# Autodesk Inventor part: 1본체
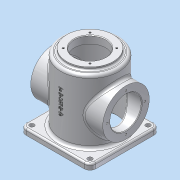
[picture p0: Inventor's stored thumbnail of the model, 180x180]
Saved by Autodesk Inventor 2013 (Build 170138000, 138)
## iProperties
Created: 2015-10
Part Number: 1본체
Material: 알루미늄 6061
Document SubType Name: Modeling
Designer: Administrator
Density: 2.71 g/cm^3
Mass: 986.025 g
Surface Area: 1037.25 cm^2
Volume: 363.847 cm^3
Author: Administrator
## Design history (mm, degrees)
sketch "스케치1"
  geometry: L1 (-60, 60)-(60, 60); L2 (60, 60)-(60, -60); L3 (60, -60)-(-60, -60); L4 (-60, -60)-(-60, 60); 3 further points
  constraints: 8 end point, 2 midpoint, 2 parallel, 2 perpendicular, 1 horizontal, 1 horizontal alignment, 1 vertical alignment
  dimensions: "d0" = 120 distance of L1.start L1.end
extrude "돌출1" new body sketch "스케치1" distance "d2" = 10; taper "d3" = 0 deg
sketch "스케치2"
  geometry: C1 r 50 at (0, 0); 1 further point
  constraints: 1 centre point, 1 coincident
  dimensions: "d4" = 100 diameter of C1
extrude "돌출2" join sketch "스케치2" distance "d6" = 110; taper "d7" = 0 deg
sketch "스케치3"
  geometry: C1 r 40 at (0, 60); 1 further point
  constraints: 1 centre point, 1 vertical alignment
  dimensions: "d8" = 80 diameter of C1; "d10" = 60 distance of C1.centre point (0, 0)
extrude "돌출3" join sketch "스케치3" stored distance "d11" = 124; taper "d12" = 0 deg
sketch "스케치4"
  geometry: C1 r 40 at (0, 0); 1 further point
  constraints: 1 centre point, 1 coincident
  dimensions: "d13" = 80 diameter of C1
extrude "돌출4" join sketch "스케치4" distance "d15" = 5; taper "d16" = 0 deg
sketch "스케치5"
  geometry: L1 (-48.178, 55.165)-(-48.178, 84.835); L2 (-48.178, 84.835)-(48.178, 84.835); L3 (48.178, 84.835)-(48.178, 55.165); L4 (48.178, 55.165)-(-48.178, 55.165); 4 further points
  constraints: 2 midpoint, 2 vertical alignment, 1 horizontal alignment, 2 other
  dimensions: "d17" = 70 distance of point (0, 70) point (0, 0)
feature "엠보싱1" sketch "스케치5" dims "d0" = 120, "d18" = 0.5, "d19" = 0
hole "구멍1" diameter "d22" = 54; stored, may be unused: countersink angle "d26" = 90 deg, drill point angle "d28" = 0 deg; dims "d20" = 10, "d21" = 10, "d23" = 6, "d24" = 54, "d25" = 13, "d27" = 124
sketch "스케치7"
  geometry: L1 (40, 125)-(-40, 125) reference; L2 (-60, 0)-(60, 0) reference; L3 (0, 125)-(0, 0); L4 (0, 125)-(27, 125); L5 (27, 112)-(45, 112); L6 (45, 112)-(45, 0); L7 (27, 125)-(27, 112); L8 (45, 0)-(0, 0)
  constraints: 12 end point, 2 parallel, 2 perpendicular, 2 point on line, 1 collinear, 1 midpoint
  dimensions: "d29" = 54 diameter of L7 L3; "d31" = 90 diameter of L6 L3; "d32" = 13 distance from line of L5.start L1
revolve "회전1" sketch "스케치7" stored, may be unused: angle "d33" = 90 deg
sketch "스케치8"
  geometry: A1 r 32.5 centre (0, 0) between (-22.981, 22.981) and (22.981, 22.981); 3 further points
  constraints: 4 point on circle, 2 horizontal alignment, 2 vertical alignment, 1 centre point, 1 coincident
  dimensions: "d34" = 65 diameter of A1; "d36" = 90 deg dimension on point (0, 0) A1.end A1.start
hole "구멍2" sketch "스케치8" at (-22.981, 22.981), (22.981, 22.981), (-22.981, -22.981), (22.981, -22.981) diameter "d38" = 3.242; stored, may be unused: countersink angle "d42" = 90 deg, drill point angle "d44" = 118 deg; dims "d39" = 8, "d40" = 54, "d41" = 13, "d43" = 10
sketch "스케치10"
  geometry: A1 r 32.5 centre (0, 0) between (32.5, 0) and (0, 32.5); 5 further points
  constraints: 4 point on circle, 3 vertical alignment, 2 horizontal alignment, 1 centre point, 2 other
  dimensions: "d45" = 60 distance of A1.centre point (0, -60); "d46" = 65 diameter of A1
hole "구멍3" sketch "스케치10" at (0, 32.5), (0, -32.5), (-32.5, 0), (32.5, 0) diameter "d47" = 3.242; stored, may be unused: countersink angle "d51" = 90 deg, drill point angle "d53" = 118 deg; dims "d48" = 8, "d49" = 54, "d50" = 13, "d52" = 10
sketch "스케치11"
  geometry: C1 r 4 at (-50, 50); C2 r 4 at (50, 50); C3 r 4 at (50, -50); C4 r 4 at (-50, -50); 1 further point
  constraints: 4 centre point, 3 equal radius, 2 horizontal alignment, 2 vertical alignment
  dimensions: "d54" = 8 diameter of C1; "d56" = 100 distance of C2.centre C1.centre; "d57" = 50 horizontal distance of point (0, 0) C1.centre; "d58" = 100 distance of C1.centre C4.centre; "d59" = 50 horizontal distance of point (0, 0) C1.centre
extrude "돌출5" cut sketch "스케치11" stored distance "d60" = 5; taper "d61" = 0 deg
fillet "모깎기1" dims "d62" = 10
chamfer "모따기1" distance "d63" = 1; stored, may be unused: second distance "d64" = 2, angle "d65" = 45 deg
chamfer "모따기2" distance "d66" = 1; stored, may be unused: second distance "d67" = 2, angle "d68" = 45 deg
chamfer "모따기3" distance "d69" = 3; stored, may be unused: second distance "d70" = 2, angle "d71" = 45 deg
fillet "모깎기3" dims "d73" = 5
fillet "모깎기4" dims "d74" = 3
fillet "모깎기5" dims "d75" = 3
fillet "모깎기7" dims "d77" = 3
fillet "모깎기9" dims "d79" = 5
fillet "모깎기10" dims "d80" = 5
fillet "모깎기11" dims "d81" = 3
node "솔리드1"
mirror "대칭1"
